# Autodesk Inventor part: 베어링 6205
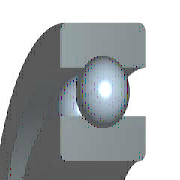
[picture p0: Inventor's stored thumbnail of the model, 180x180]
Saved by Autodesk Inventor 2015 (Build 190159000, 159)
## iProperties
Created: 2015-10
Part Number: 베어링 6205
Material: 강, 연강
Description: 깊은 그루브 볼 베어링
Document SubType Name: Modeling
Standard: KS B 2023
Designer: mdu
Standards Organization: KS
Language: ko-KR
Size Designation: 6205 - 25 x 52 x 15
Categories: <MemberInstance><Categories><Category DisplayName="샤프트 부품" InternalName="7f7aeb1f-a693-4053-b835-cee3144e0d98" Mnemonic="SHFT"><Category DisplayName="베어링" Inter
Density: 1 g/cm^3
Appearance: 노란색
IsCustomPart: 1
Author: mdu
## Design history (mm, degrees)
sketch "스케치" dims "d0" = 7.02 (= -0.26 x WD + 0.26 x BD)
  geometry: L1 (3.99, 19.25)-(11.01, 19.25); L2 (7.5, 19.25)-(7.5, 15.74); L3 (7.5, 19.25)-(7.5, 22.76); L4 (4.892, 16.901)-(0, 16.901); L5 (0, 12.5)-(15, 12.5); L6 (4.892, 21.599)-(0, 21.599); L7 (0, 26)-(15, 26); L8 (15, 12.5)-(15, 16.901); L9 (10.108, 16.901)-(15, 16.901); L10 (10.108, 21.599)-(15, 21.599); L11 (15, 26)-(15, 21.599); L12 (-1.4, 0)-(8.4, 0) reference; L13 (0, -0.3)-(0, 5.3) reference
  constraints: 22 end point, 4 point on line, 2 collinear, 2 perpendicular, 2 symmetric about line, 1 midpoint, 1 parallel, 14 other
  dimensions: "d9" = 25 diameter of L5 L12 (= WD); "d11" = 52 diameter of L7 L12 (= BD); "d12" = 15 distance between parallel lines of L8 L13 (= KB); "d13" = 33.802 diameter of L9 L12 (= 0.326 x BD + 0.674 x WD)
revolve "본체" stored, may be unused: angle "d6" = 90 deg
revolve "볼" stored, may be unused: angle "d7" = 90 deg
pattern_circular "IDS_ARRAYBALL[SIMPL:T]" dims angle "d3" = 360 deg
body "Solid1"
fillet "모깎기1" dims "d1" = 1 (= KRS)
other parameters: "WD" = 25 [user parameter; used in 5 equation terms], "BD" = 52 [user parameter; used in 5 equation terms], "KB" = 15 [user parameter; used in 1 equation term], "KRS" = 1 [user parameter; used in 1 equation term], "d4" = 0, "d5" = 0, "d8" = 0, "d14" = 0, "d15" = 0, "BBA" = 0 [user parameter], "BC0" = 7800000 [user parameter], "BC" = 1.4e+07 [user parameter], "BR" = 26 (= 0.5 x BD) [user parameter], "WR" = 12.5 (= 0.5 x WD) [user parameter]
